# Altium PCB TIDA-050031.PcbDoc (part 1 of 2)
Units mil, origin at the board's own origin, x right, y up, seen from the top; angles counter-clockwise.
Board outline 3300 x 2400 mil, 4 copper layers (Top Layer, Signal Layer 1, Signal Layer 2, Bottom Layer), stack 65.634 mil thick; 87 components, 39 nets, 206 pads, 178 vias.
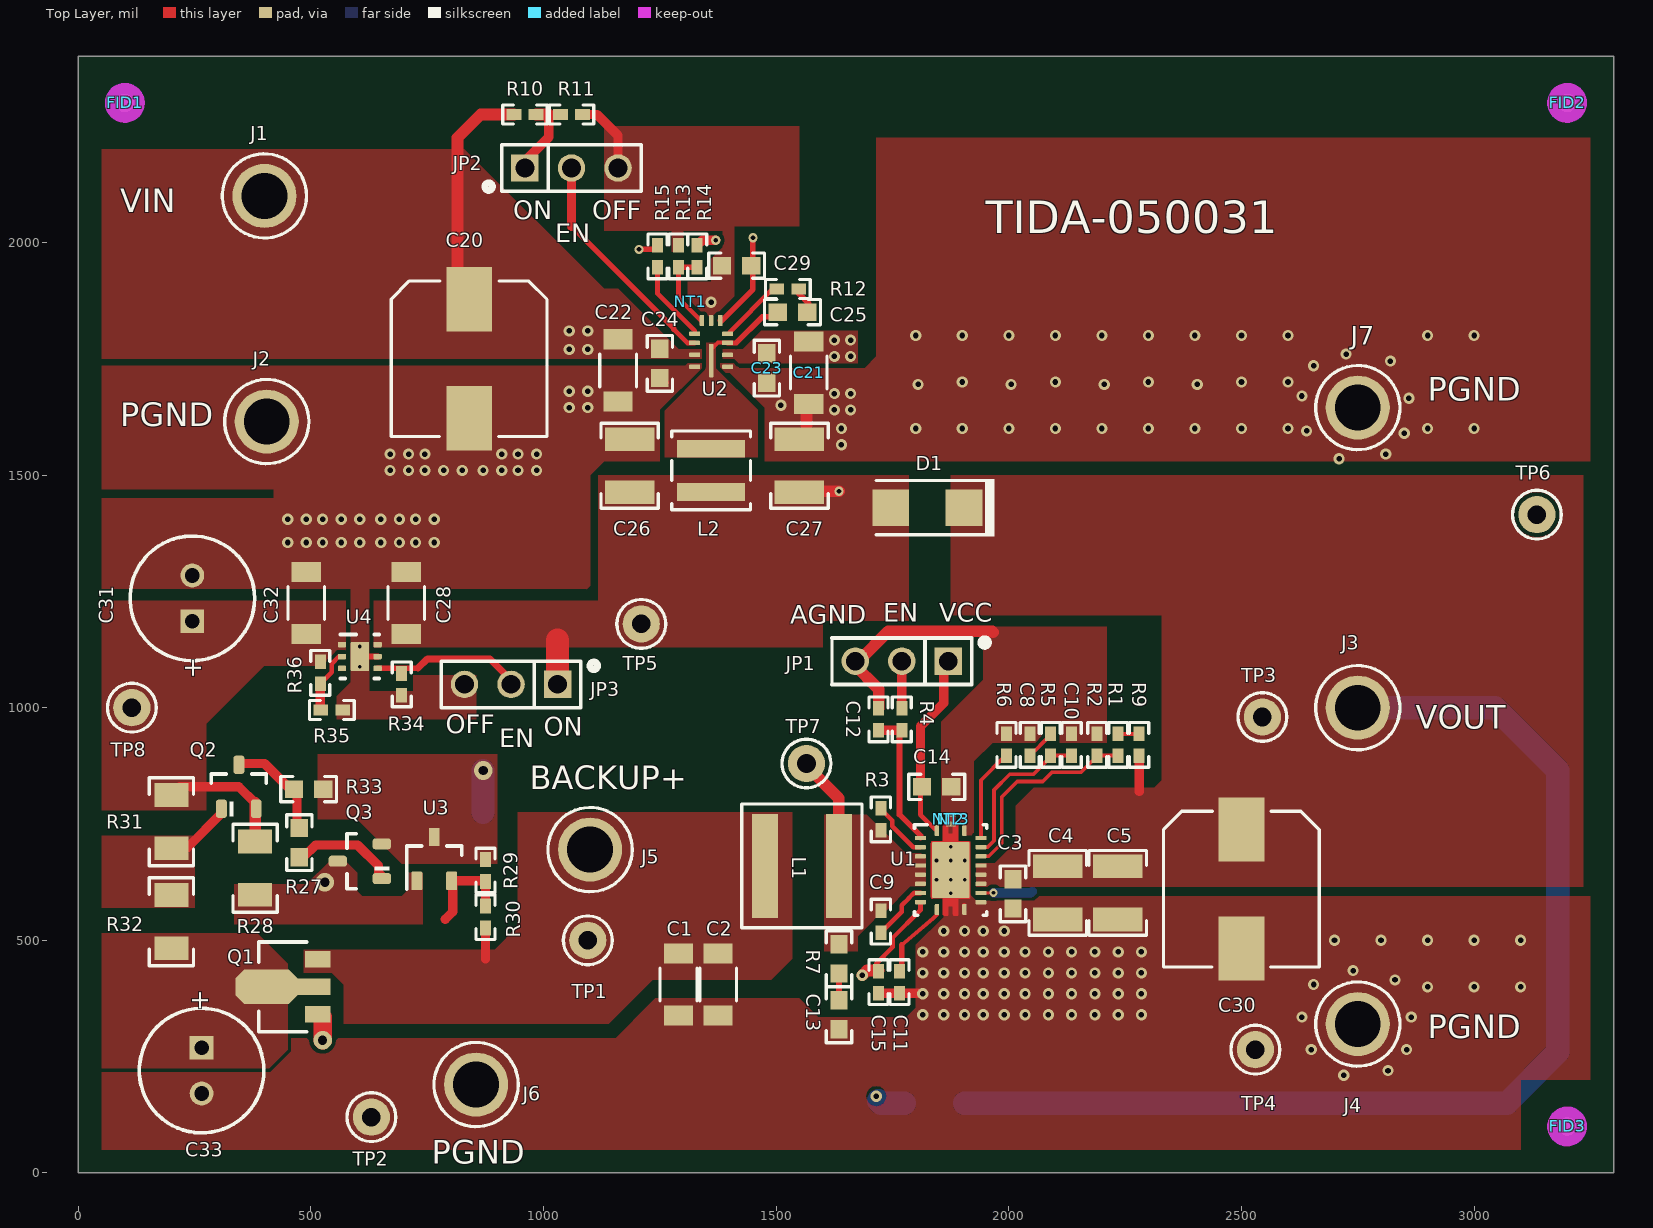
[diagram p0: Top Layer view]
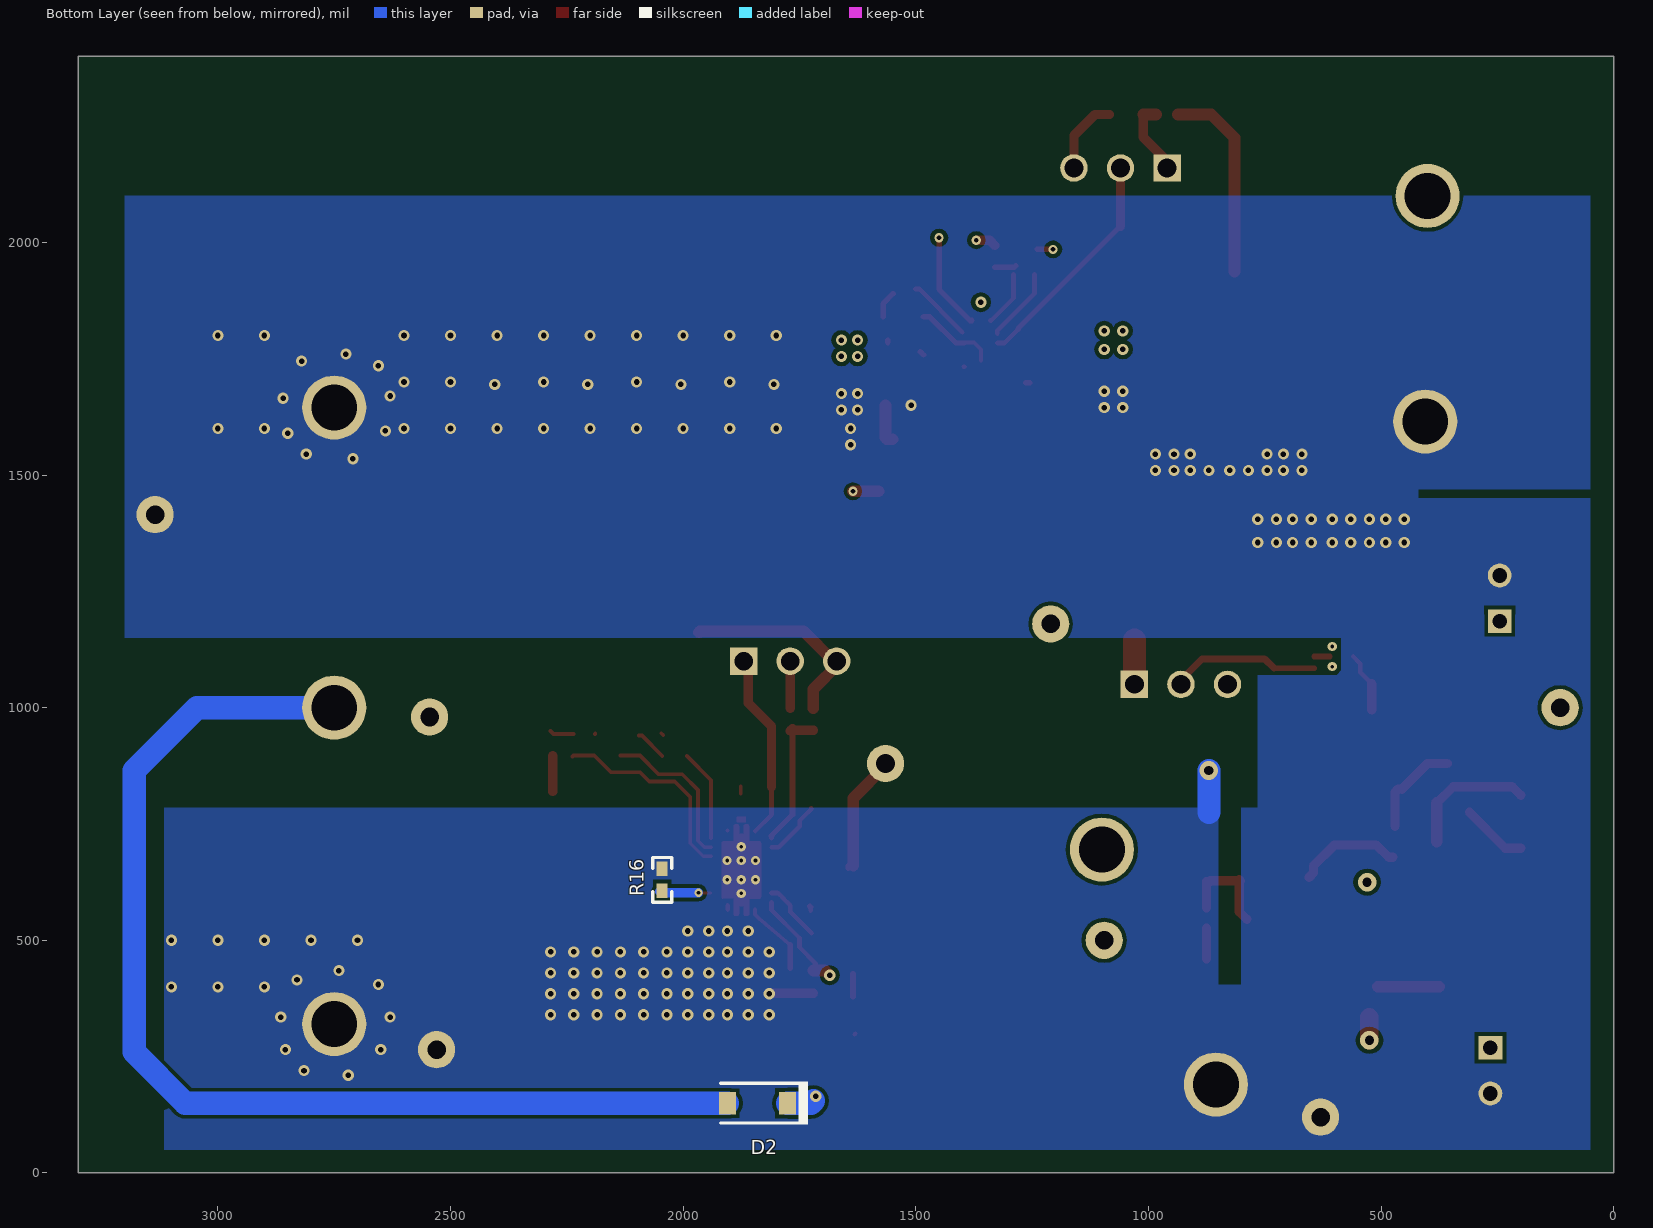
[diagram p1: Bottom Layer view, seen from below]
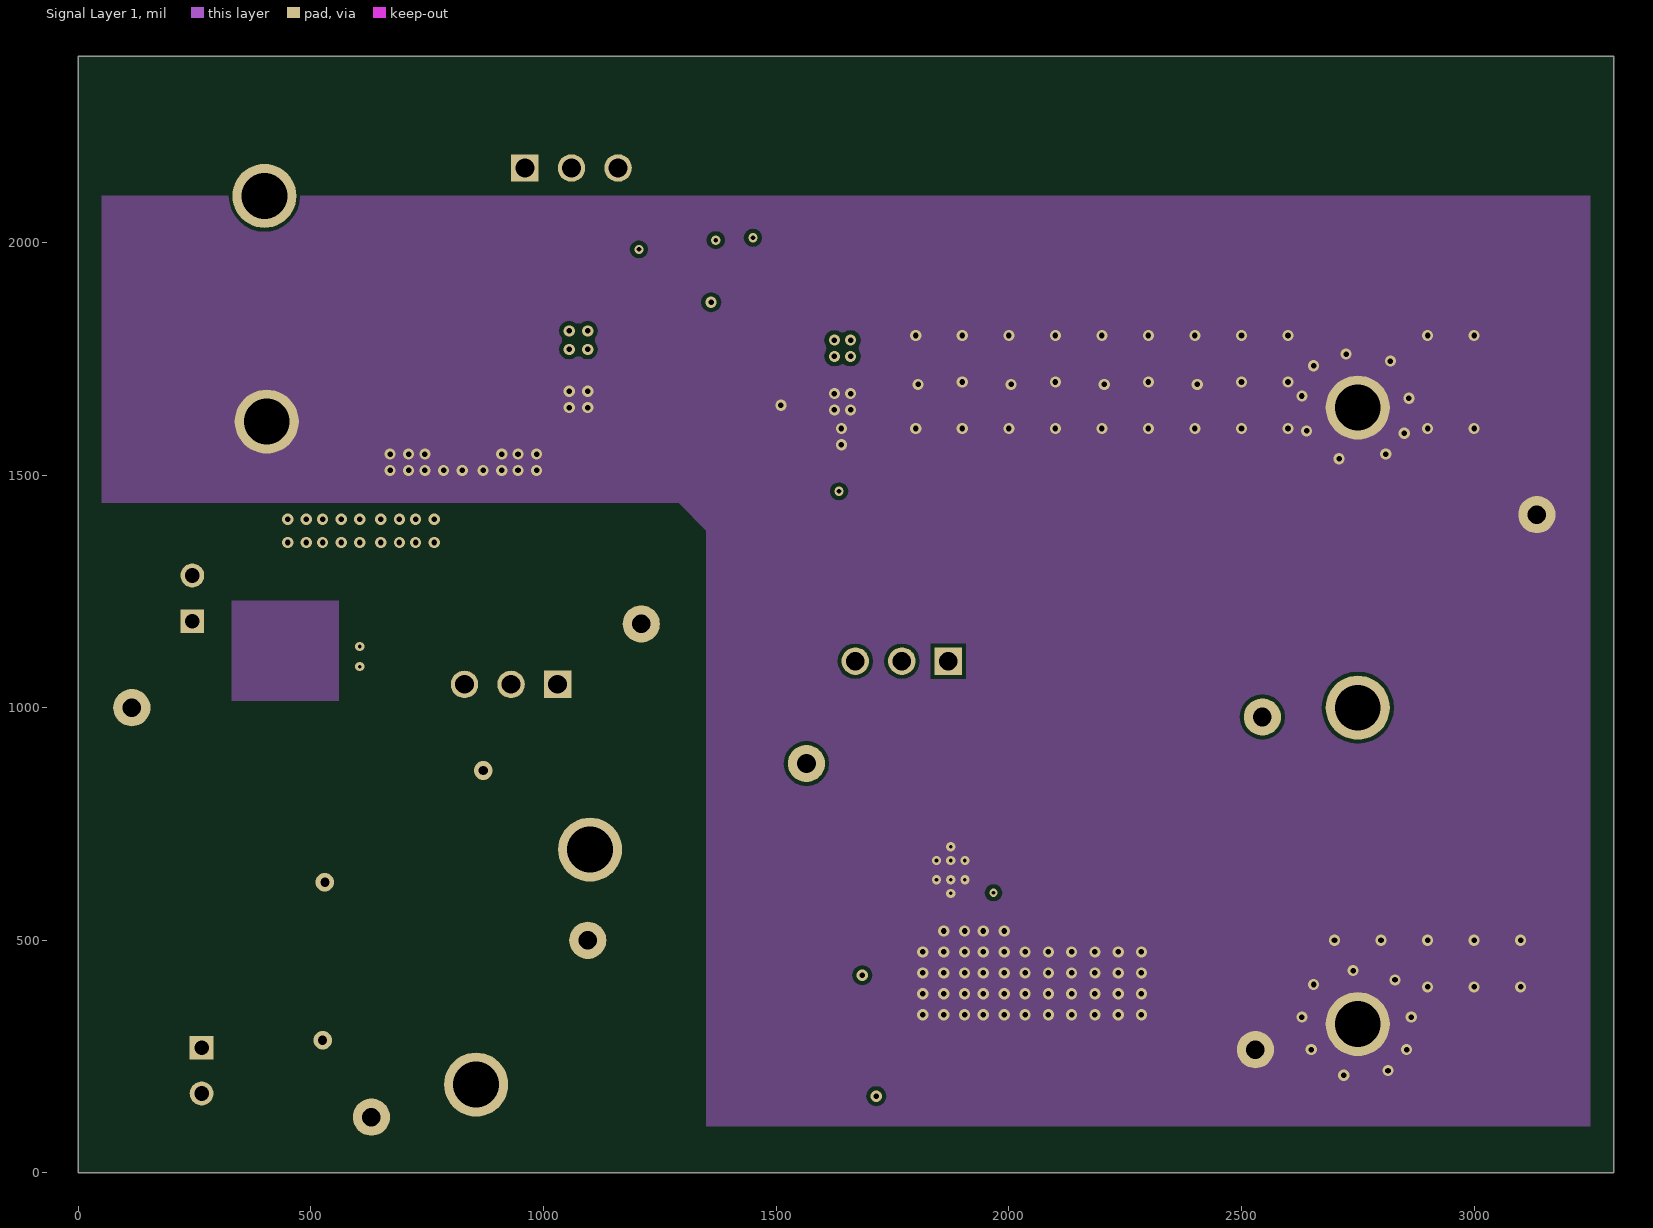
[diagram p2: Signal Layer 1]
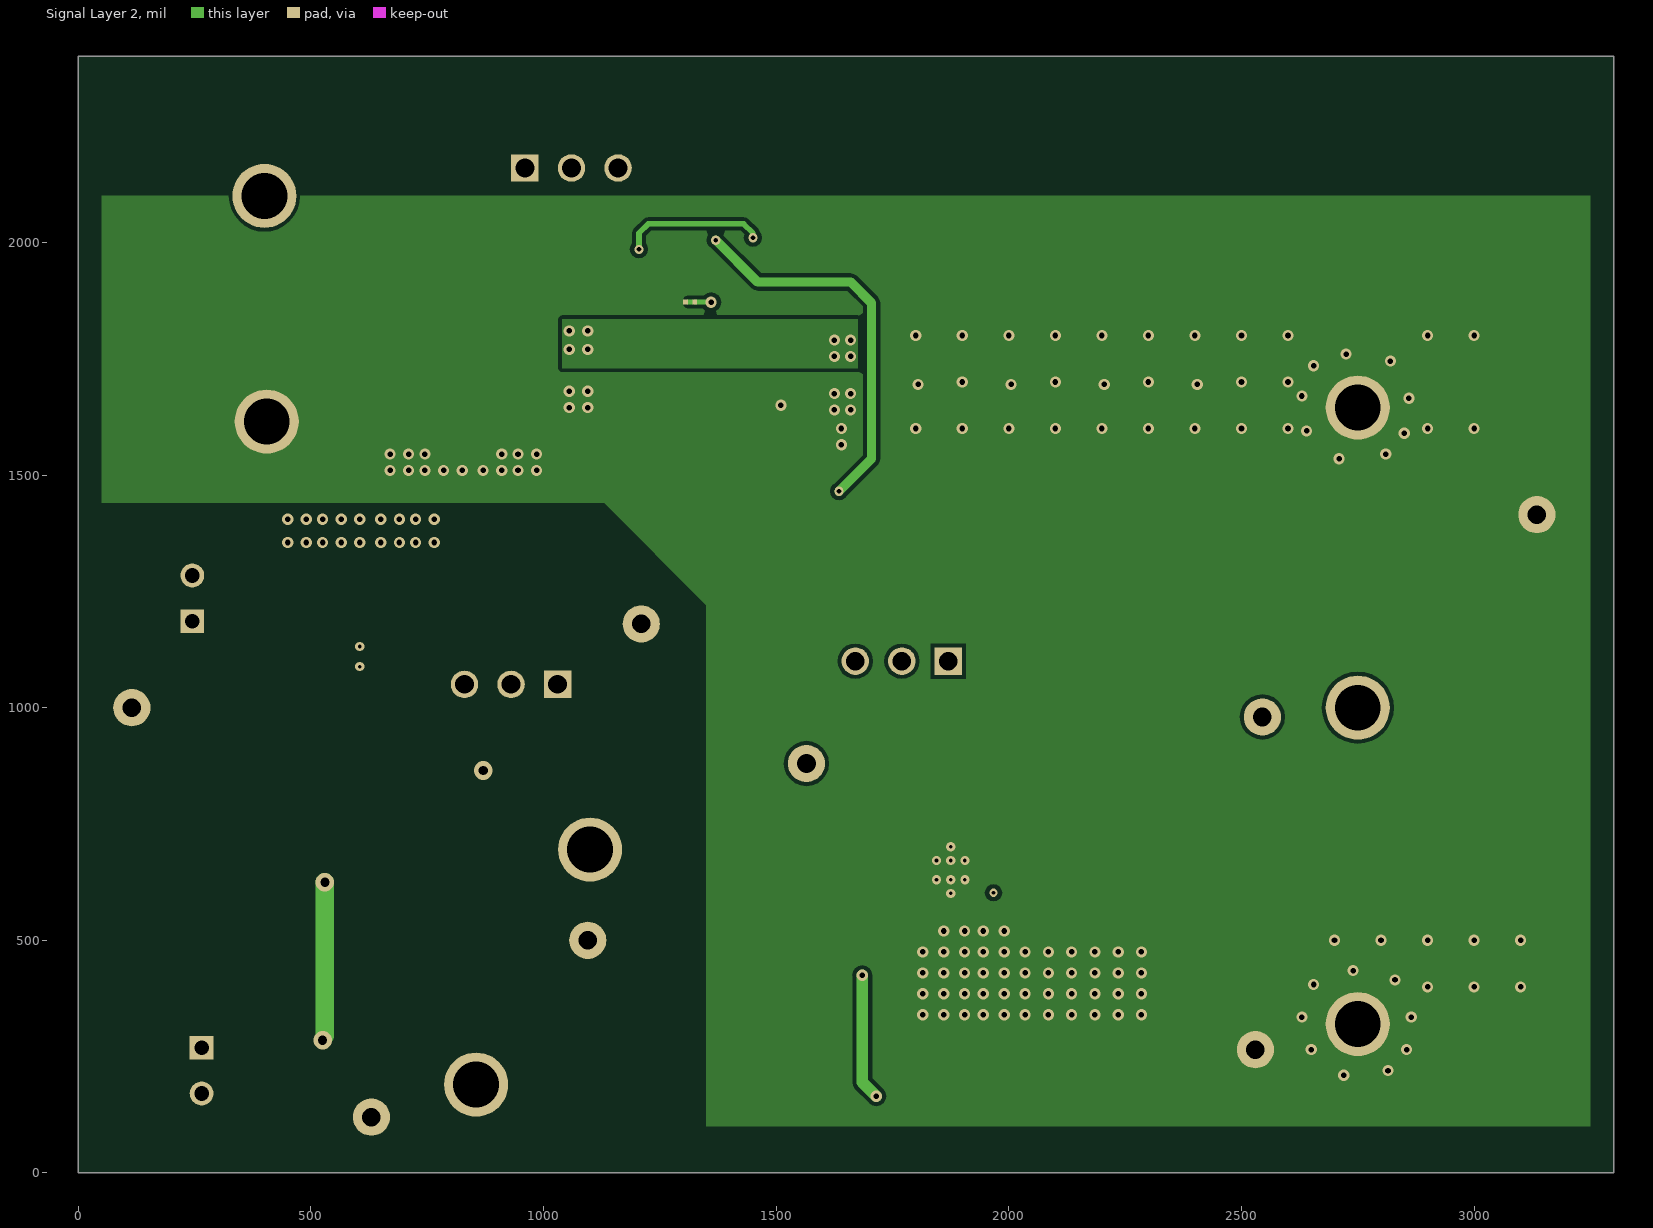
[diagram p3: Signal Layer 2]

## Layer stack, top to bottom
Top Solder: solder mask 0.4, Solder Resist, Dk 3.5
Top Layer: signal copper 1.4
Dielectric 2: core 20, Dk 4.2
Signal Layer 1: signal copper 1.417
Dielectric 3: core 20, Dk 4.2
Signal Layer 2: signal copper 1.417
Dielectric1: core 20, FR-4, Dk 4.8
Bottom Layer: signal copper 1.4
Bottom Solder: solder mask 0.4, Solder Resist, Dk 3.5

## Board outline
0,0 3300,0 3300,2400 0,2400

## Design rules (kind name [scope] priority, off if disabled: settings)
AcuteAngle [All] p1: minimum=4.50000000000000E+0001 checktracksonly=FALSE
AssemblyTestPointUsage [All] p1: valid=2
BoardOutlineClearance BoardOutlineClearance_MountingHoles [OnCopper and InComponentClass('Mounting Holes')] p1: gap=40 ignorepadtopadclearanceinfootprint=FALSE
BoardOutlineClearance BoardOutlineClearance_Poly [OnCopper and IsPoly] p2: gap=25 ignorepadtopadclearanceinfootprint=FALSE
BoardOutlineClearance [OnCopper and Not InComponentClass('Logo') and not InComponentClass('FiducialMark') and not InRegion(1000,500,4000,800) and not InPoly] p3: gap=75 ignorepadtopadclearanceinfootprint=FALSE
Clearance Clearance_Keepouts [((IsTrack Or IsArc) And Not InPoly) And IsFree and IsKeepOut vs ((IsTrack Or IsArc) And Not InPoly) And IsFree and IsKeepOut] p1: gap=0 ignorepadtopadclearanceinfootprint=FALSE
Clearance Clearance_Poly [InPolygon] p2: gap=10 ignorepadtopadclearanceinfootprint=FALSE except(0: Arc-Hole Track-Hole SMDPad-Hole THPad-Hole Via-Hole Fill-Hole Poly-Hole Region-Hole Text-Hole; 8: Arc-Fill Arc-Poly Arc-Region Track-Fill Track-Poly Track-Region SMDPad-Fill SMDPad-Poly SMDPad-Region THPad-Fill THPad-Poly THPad-Region Fill-Fill Fill-Poly Fill-Region Poly-Poly Poly-Region Region-Region; 9: Via-Fill Via-Poly Via-Region)
Clearance Clearance_FiducialMark [IsKeepOut and InComponentClass('FiducialMark') vs IsPad and InComponentClass('FiducialMark')] p3: gap=0 ignorepadtopadclearanceinfootprint=FALSE
Clearance [All] p4: gap=7.87 ignorepadtopadclearanceinfootprint=FALSE except(0: Arc-Hole Track-Hole SMDPad-Hole THPad-Hole Via-Hole Fill-Hole Poly-Hole Region-Hole Text-Hole)
ComponentClearance ComponentClearance_MountingHoles_FiducialMarks [InComponentClass('Mounting Holes') vs InComponentClass('FiducialMark')] p1: gap=0 collisioncheckmode=3 verticalgap=0 showdistances=FALSE
ComponentClearance ComponentClearance_Shunt [InComponentClass('Header') vs InComponentClass('Shunt')] p2: gap=0 collisioncheckmode=3 verticalgap=0 showdistances=FALSE
ComponentClearance ComponentClearance_Logo [InComponentClass('Logo')] p3: gap=10 collisioncheckmode=3 verticalgap=10 showdistances=FALSE
ComponentClearance ComponentClearance_ScrewToNut [(HasFootprint('NY PMS 440 0025 PH')) vs (HasFootprint('Keystone_1902C'))] p4: gap=5 collisioncheckmode=3 verticalgap=10 showdistances=FALSE
ComponentClearance ComponentClearance_MountingHoles [InComponentClass('Mounting Holes')] p5: gap=10 collisioncheckmode=3 verticalgap=100000 showdistances=FALSE
ComponentClearance ComponentClearance_SmallPassives [HasFootprint('0201*') or HasFootprint('0402*') or HasFootprint('0508') or HasFootprint('0603*') or HasFootprint('0612') or HasFootprint('0805*') or HasFootprint('0815*') or HasFootprint('0830*') or HasFootprint('1206*') or HasFootprint('1210*') or HasFootprint('1808*') or HasFootprint('1812*') or HasFootprint('1825*') or HasFootprint('2010*') or HasFootprint('2220*') or HasFootprint('2225*') or HasFootprint('2512*') or HasFootprint('2728*') or HasFootprint('3518*') vs HasFootprint('0201*') or HasFootprint('0402*') or HasFootprint('0508') or HasFootprint('0603*') or HasFootprint('0612') or HasFootprint('0805*') or HasFootprint('0815*') or HasFootprint('0830*') or HasFootprint('1206*') or HasFootprint('1210*') or HasFootprint('1808*') or HasFootprint('1812*') or HasFootprint('1825*') or HasFootprint('2010*') or HasFootprint('2220*') or HasFootprint('2225*') or HasFootprint('2512*') or HasFootprint('2728*') or HasFootprint('3518*')] p6: gap=0 collisioncheckmode=3 verticalgap=10 showdistances=FALSE
ComponentClearance ComponentClearance_THtoSMT [IsThruComponent vs IsSMTComponent] p7: gap=5 collisioncheckmode=3 verticalgap=5 showdistances=FALSE
ComponentClearance ComponentClearance_THtoTH [IsThruComponent vs IsThruComponent] p8: gap=5 collisioncheckmode=3 verticalgap=5 showdistances=FALSE
ComponentClearance [All] p9: gap=0 collisioncheckmode=3 verticalgap=0 showdistances=FALSE
DiffPairsRouting [All] p1: maxlimit=100 minlimit=10 mostfreqgap=10 toplayer_minwidth=15 toplayer_maxwidth=15 toplayer_prefwidth=15 midlayer1_minwidth=15 midlayer1_maxwidth=15 midlayer1_prefwidth=15 midlayer2_minwidth=15 midlayer2_maxwidth=15 midlayer2_prefwidth=15 bottomlayer_minwidth=15 bottomlayer_maxwidth=15 bottomlayer_prefwidth=15 maxuncoupledlength=1000
FabricationTestPointUsage TestPointUsage [All] p1: valid=2 allowmultiple=FALSE
FabricationTestpoint Testpoint [All] p1: side=3 testpointundercomponent=TRUE minsize=40 maxsize=100 preferedsize=60 minholesize=0 maxholesize=40 preferedholesize=32 testpointgrid=1 allowsidetop=TRUE allowsidebottom=TRUE usegrid=TRUE gridtolerance=0.01
FanoutControl Fanout_LCC [IsLCC] p1: bgadir=Out bgaviamode=Centered fanoutstyle=Auto fanoutdirection=Alternating viagrid=1 // Fanout_LCC (Default Rule)
FanoutControl Fanout_BGA [IsBGA] p2: bgadir=Out bgaviamode=Centered fanoutstyle=Auto fanoutdirection=Alternating viagrid=1 // Fanout_BGA (Default Rule)
FanoutControl Fanout_Default [All] p4: bgadir=Out bgaviamode=Centered fanoutstyle=Auto fanoutdirection=Alternating viagrid=1 // Fanout_Default (Default Rule)
FanoutControl Fanout_Small [(CompPinCount < 5)] p5: bgadir=Out bgaviamode=Centered fanoutstyle=Auto fanoutdirection=OutThenIn viagrid=1 // Fanout_Small (Default Rule)
HoleSize [All] p1: absolutevalues=TRUE maxlimit=251 minlimit=7.87 maxpercent=80.000 minpercent=20.000
MinimumAnnularRing MinimumAnnularRing_ThermalPadVias [IsVia and InAnyComponent] p1: minimumring=5.91
MinimumAnnularRing [All] p2: minimumring=8
MinimumSolderMaskSliver MinimumSolderMaskSliver_Logo [InComponentClass('Logo') vs InComponentClass('Logo')] p1: minsoldermaskwidth=0.7
MinimumSolderMaskSliver [All] p2: minsoldermaskwidth=3.94
PlaneClearance [All] p1: clearance=15
PlaneConnect [All] p1: planeconnectstyle=Direct reliefexpansion=10 reliefentries=4 reliefconductorwidth=10 reliefairgap=10
PolygonConnect [All] p1: connectstyle=Direct reliefconductorwidth=10 reliefentries=4 polygonreliefangle="90 Angle" airgapwidth=10
RoutingVias ThermalPadVias [IsVia and InAnyComponent] p1: holewidth=7.87 width=19.68 viastyle="Through Hole" minholewidth=7.87 minwidth=19.68 maxholewidth=12.99 maxwidth=23.62
RoutingVias [All] p2: holewidth=16 width=34 viastyle="Through Hole" minholewidth=7.87 minwidth=26 maxholewidth=40 maxwidth=65
SilkToBoardRegionClearance [Not ((IsComment or IsDesignator) And (Hide <> 'False')) and not InRegion(1000,500,4000,800)] p1:
SilkToSilkClearance SilkToSilkClearance_Pb-FreeLogo [(HasFootprint('Pb-Free_Overlay_Medium') OR HasFootprint('Pb-Free_Overlay_Small')) vs (HasFootprint('Pb-Free_Overlay_Medium') OR HasFootprint('Pb-Free_Overlay_Small'))] p1: silktosilkclearance=0
SilkToSilkClearance [All] p2: silktosilkclearance=4
SilkToSolderMaskClearance SilkToComponentPadClearance [(IsPad or IsFill or IsRegion) and InAnycomponent] p1: minsilkscreentomaskgap=5 clearancetoexposedcopper=TRUE
SilkToSolderMaskClearance "Silk to Solder Mask Opening" [All] p2: minsilkscreentomaskgap=4 clearancetoexposedcopper=FALSE
SolderMaskExpansion [All] p1: expansion=1.97
Width [All] p1: maxlimit=100 minlimit=6 preferedwidth=10 checkconnectedcopper=TRUE
14 further rules are at their usual default settings.

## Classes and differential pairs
component class TIDA-050031_Hardware: !PCB FID1 FID2 FID3
component class FiducialMark: FID1 FID2 FID3
component class Header: JP1 JP2 JP3

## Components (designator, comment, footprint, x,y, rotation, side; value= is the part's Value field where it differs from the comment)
C1 "Capacitor" 1206_180 1290,405 r270 top value=22uF
C2 "Capacitor" 1206_180 1375,405 r270 top value=22uF
C3 "Capacitor" 0603 2009,600 r270 top value=1uF
C4 "Capacitor" 1210_270 2105,602 r270 top value=22uF
C5 "Capacitor" 1210_270 2234,602 r270 top value=22uF
C8 "Capacitor" 0402 2045,920 r90 top value=4700pF
C9 "Capacitor" 0402 1725,540 r270 top value=0.1uF
C10 "Capacitor" 0402 2135,920 r90 top value=47pF
C11 "Capacitor" 0402 1765,410 r90 top value=0.047uF
C12 "Capacitor" 0402 1720,975 r90 top value=0.1uF
C13 "Capacitor" 0603 1635,340 r270 top value=1000pF
C14 "Capacitor" 0603 1845,830 r180 top value=4.7uF
C15 "Capacitor" 0402 1720,410 r270 top value=0.1uF
C20 "EEHZA1H680P" SM_RADIAL_8MM 840,1750 r270 top value=68uF
C21 "CGA5L1X7R1H106K160AC" 1206_190 1570,1720 r270 top value=10uF
C22 "CGA5L1X7R1H106K160AC" 1206_190 1160,1725 r270 top value=10uF
C23 "C1608X5R1H105K080AB" 0603 1480,1730 r270 top value=1uF
C24 "C1608X5R1H105K080AB" 0603 1250,1740 r270 top value=1uF
C25 "C1608X5R1H474K080AB" 0603 1535,1850 r0 top value=0.47uF
C26 "Capacitor" 1210_270 1185,1520 r90 top value=22uF
C27 "Capacitor" 1210_270 1550,1520 r90 top value=22uF
C28 "Capacitor" 1206_180 705,1225 r90 top value=22uF
C29 "Capacitor" 0603 1415,1950 r0 top value=4.7uF
C30 "EEHZA1E221P" SM_RADIAL_8MM 2500,610 r270 top value=220uF
C31 "ECA-0JM471B" M_630x1120 245,1235 r90 top value=470uF
C32 "Capacitor" 1206_180 490,1225 r90 top value=22uF
C33 "ECA-0JM471B" M_630x1120 265,220 r270 top value=470uF
D1 "SL12-E3/61T" SMA 1825,1430 r180 top value=20V
D2 "1N4148W-7-F" SOD-123 1840,150 r0 bottom value=100V
FID1 "Fiducial" Fiducial10-20 100,2300 r0 top
FID2 "Fiducial" Fiducial10-20 3200,2300 r0 top
FID3 "Fiducial" Fiducial10-20 3200,100 r0 top
J1 "Suggest using a net name here" Keystone1502-2 400,2100 r0 top value=Double
J2 "Turret" Keystone1502-2 405,1615 r0 top
J3 "Turret" Keystone1502-2 2750,1000 r0 top
J4 "Turret" Keystone1502-2 2750,320 r0 top
J5 "Turret" Keystone1502-2 1100,695 r0 top
J6 "Turret" Keystone1502-2 855,190 r0 top
J7 "Turret" Keystone1502-2 2750,1645 r0 top
JP1 "Header_3x1_Launchpad" CONN_PEC03SAAN 1770,1100 r180 top
JP2 "Header_3x1_Launchpad" CONN_PEC03SAAN 1060,2160 r0 top
JP3 "Header_3x1_Launchpad" CONN_PEC03SAAN 930,1050 r180 top
L1 "Inductor_Iron" XAL6030 1555,660 r0 top value=2.2uH
L2 "XAL4020-222MEB" XAL4020 1360,1510 r270 top value=2.2uH
NT1 "Net-Tie" Net-Tie_10mil#1 1315,1872 r180 top net-tie
NT2 "Net-Tie" Net-Tie_10mil#2 1870,760 r90 top net-tie
NT3 "Net-Tie" Net-Tie_10mil#2 1880,760 r90 top net-tie
Q1 "2DD1664R-13" SOT-89-3 440,400 r180 top value="32 V"
Q2 "BC857C-7-F" SOT-23 345,830 r90 top value="45 V"
Q3 "BC847CLT1G" SOT-23 605,670 r180 top value="45 V"
R1 "CRCW0402280KFKED" 0402 2235,920 r90 top value=280k
R2 "CRCW040249K9FKED" 0402 2190,920 r270 top value=49.9k
R3 "Resistor" 0402 1725,760 r270 top value=392k
R4 "Resistor" 0402 1770,975 r90 top value=0
R5 "Resistor" 0402 2090,920 r270 top value=17.4k
R6 "Resistor" 0402 1995,920 r270 top value=49.9k
R7 "Resistor" 0603 1635,460 r270 top value=2.05
R9 "Resistor" 0402 2280,920 r270 top value=49.9
R10 "CRCW0402402KFKED" 0402 960,2275 r180 top value=402k
R11 "CRCW0402133KFKED" 0402 1060,2275 r180 top value=133k
R12 "RC0402JR-070RL" 0402 1525,1900 r0 top value=0
R13 "CRCW040249K9FKED" 0402 1290,1970 r270 top value=49.9k
R14 "CRCW0402402KFKED" 0402 1330,1970 r90 top value=402k
R15 "Resistor" 0402 1245,1970 r90 top value=17.4k
R16 "Resistor" 0402 2045,630 r90 bottom value=0
R27 "CRCW0603100RFKEA" 0603 475,710 r270 top value=100
R28 "CRCW120633R0JNEA" 1206 380,655 r270 top value=33
R29 "CRCW0402100KFKED" 0402 875,650 r270 top value=100k
R30 "CRCW040240K2FKED" 0402 875,550 r270 top value=40.2k
R31 "RC1206FR-076R49L" 1206 200,755 r270 top value=6.49
R32 "RC1206FR-076R49L" 1206 200,540 r270 top value=6.49
R33 "CRCW0603499RFKEA" 0603 495,825 r180 top value=499
R34 "CRCW0402100KFKED" 0402 695,1050 r90 top value=100k
R35 "CRCW0402165KFKED" 0402 545,995 r180 top value=165k
R36 "CRCW0402499KFKED" 0402 520,1075 r90 top value=499k
TP1 "5003" Keystone5003 1095,500 r90 top value=Orange
TP2 "5003" Keystone5003 630,120 r90 top value=Orange
TP3 "5003" Keystone5003 2545,980 r90 top value=Orange
TP4 "5003" Keystone5003 2530,265 r0 top value=Orange
TP5 "5003" Keystone5003 1210,1180 r90 top value=Orange
TP6 "5003" Keystone5003 3135,1415 r90 top value=Orange
TP7 "5003" Keystone5003 1565,880 r270 top value=Orange
TP8 "5003" Keystone5003 115,1000 r90 top value=Orange
U1 "TPS61088QRHLRQ1" RHL0020A 1875,651 r0 top
U2 "LMR33630AQRNXRQ1" RNX0012B 1360,1777.09 r180 top
U3 "ATL431AIDBZR" DBZ0003A_N 765,675 r90 top
U4 "TPS7A2501DRVR" DRV0006A 605,1110 r0 top

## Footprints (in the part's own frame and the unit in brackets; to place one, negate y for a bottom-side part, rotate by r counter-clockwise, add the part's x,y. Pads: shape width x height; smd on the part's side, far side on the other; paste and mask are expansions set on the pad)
0402 [mm] "0402 from SM-752 data"
  rect 0.8x0.6 smd: 1(-0.6,0) 2(0.6,0)
  silkscreen extent -1.22,-0.52 1.22,0.52, body extent -0.55,-0.3 0.55,0.3, height 0.6
0603 [mm] "0603 from SM-752 data"
  rect 1x0.95 smd: 1(-0.8,0) 2(0.8,0)
  silkscreen extent -1.52,-0.69 1.52,0.69, body extent -0.87,-0.47 0.87,0.47, height 1
1206 [mm] "1206 from SM-752 data"
  rect 1.3x1.85 smd: 1(-1.45,0) 2(1.45,0)
  silkscreen extent -2.4,-1.21 2.4,1.21, body extent -1.7,-0.9 1.7,0.9, height 1.35
1206_180 [mm] "1206_180"
  rect 1.1x1.6 smd: 1(-1.7,0) 2(1.7,0)
  silkscreen extent -0.9,-1 0.9,1, body extent -1.75,-0.95 1.75,0.95, height 1.8
1206_190 [mm] "1206_190"
  rect 1.1x1.6 smd: 1(-1.7,0) 2(1.7,0)
  silkscreen extent -0.9,-1 0.9,1, body extent -1.75,-0.95 1.75,0.95, height 1.9
1210_270 [mm] "1210"
  rect 1.3x2.7 smd: 1(-1.45,0) 2(1.45,0)
  silkscreen extent -2.32,-1.57 2.32,1.57, body extent -1.7,-1.35 1.7,1.35, height 2.7
CONN_PEC03SAAN [mm] "SULLINS"
  rect 1.5x1.5 hole 1.016: 1(-2.54,0)
  round 1.5 hole 1.016: 2(0,0) 3(2.54,0)
  silkscreen extent -4.72,-1.27 3.81,1.27, body extent -3.84,-1.3 3.84,1.3, height 8.38
DBZ0003A_N [mm] "SOT23, 3-Leads, Body 2.9x1.3mm, Pitch 0.95mm, Lead Span 2.4mm, IPC Medium Density"
  rrect17% 1x0.6 smd: 1(-1.2,0.95) 2(-1.2,-0.95) 3(1.2,0)
  silkscreen extent -1.65,-1.5 0.7,1.5, body extent -1.26,-1.46 1.26,1.46, height 0.98
DRV0006A [mm] "SON, 6-Leads, Body 2x2mm, Pitch 0.65mm, Thermal Pad 1.6x1mm, TI Recommended"
  rrect33% 0.45x0.3 smd: 1(-0.975,0.65) 2(-0.975,0) 3(-0.975,-0.65) 4(0.975,-0.65) 5(0.975,0) 6(0.975,0.65)
  rrect14% 1x0.7 on Top Paste: 7(0,-0.45) 7(0,0.45)
  rrect10% 1x1.6 smd paste-0.5: 7(0,0)
  silkscreen extent -1.05,-1.2 1.05,1.2, body extent -1.05,-1.05 1.05,1.05, height 0.81
Fiducial10-20 [mm]
  round 1 smd mask+0.5: 1(0,0)
  Top Layer keep-out circle w1.178: c0,0 r0.5
Keystone1502-2 [mm] "Double Turret"
  round 3.5 hole 2.5: 1(0,0)
  silkscreen extent -2.3,-2.3 2.3,2.3, body extent -1.6,-1.6 1.59,1.6, height 5.62
Keystone5003 [mil] "For Keystone 500x miniature loop terminals"
  round 80 hole 40: 1(0,0)
  silkscreen extent -52,-52 52,52, body extent -49,-49 49,49, height 182
M_630x1120 [mm] "TH, 2-Leads, Dia 6.3mm, Pin Spacing 2.5mm"
  rect 1.3x1.3 hole 0.8: 1(-1.25,0)
  round 1.3 hole 0.8: 2(1.25,0)
  silkscreen extent -3.4,-3.4 3.4,3.4, body extent -3.37,-3.39 3.4,3.39, height 12.21
Net-Tie_10mil#1 [mil] "10mil net tie, no solder mask opening, no solder paste"
  rect 10x10 on Mid2 paste-5 mask-5: 1(-10,0) 2(10,0)
  Signal Layer 2 region: -6,5 6,5 6,-5 -6,-5
Net-Tie_10mil#2 [mil] "10mil net tie, no solder mask opening, no solder paste"
  rect 10x10 smd paste-5 mask-5: 1(-10,0) 2(10,0)
  Top Layer region: -6,5 6,5 6,-5 -6,-5
RHL0020A [mm] "QFN, 20-Leads, Body 4.5x3.5mm, Pitch 0.5mm, Thermal Pad 3.05x2.05mm, TI Recommended"
  rrect42% 0.24x0.6 smd: 1(-0.75,2.15) 10(-0.75,-2.15) 11(0.75,-2.15) 20(0.75,2.15)
  rrect42% 0.6x0.24 smd: 2(-1.65,1.75) 3(-1.65,1.25) 4(-1.65,0.75) 5(-1.65,0.25) 6(-1.65,-0.25) 7(-1.65,-0.75) 8(-1.65,-1.25) 9(-1.65,-1.75) 12(1.65,-1.75) 13(1.65,-1.25) 14(1.65,-0.75) 15(1.65,-0.25) 16(1.65,0.25) 17(1.65,0.75) 18(1.65,1.25) 19(1.65,1.75)
  rrect12% 0.92x0.85 on Top Paste: 21(-0.56,-1.05) 21(-0.56,0) 21(-0.56,1.05) 21(0.56,-1.05) 21(0.56,0) 21(0.56,1.05)
  rrect5% 2.05x3.05 smd paste-2 mask+0: 21(0,0)
  Top Layer region: -0.975,-1.575 -0.425,-1.575 -0.425,-2.4 -0.417,-2.438 -0.396,-2.471 -0.363,-2.492 -0.325,-2.5 -0.325,-2.5 -0.225,-2.5 -0.187,-2.492 -0.154,-2.471 -0.133,-2.438 -0.125,-2.4 -0.125,-2.4 -0.125,-1.975 0.125,-1.975 0.125,-2.4 0.133,-2.438 0.154,-2.471 0.187,-2.492 0.225,-2.5 0.225,-2.5 0.325,-2.5 0.363,-2.492 0.396,-2.471 0.417,-2.438 0.425,-2.4 0.425,-2.4 0.425,-1.575 0.975,-1.575 1.013,-1.567 1.046,-1.546 1.067,-1.513 1.075,-1.475 1.075,-1.475 1.075,1.475 1.067,1.513 1.046,1.546 1.013,1.567 0.975,1.575 0.975,1.575 0.425,1.575 0.425,2.4 0.417,2.438 0.396,2.471 0.363,2.492 0.325,2.5 0.325,2.5 0.225,2.5 0.187,2.492 0.154,2.471 0.133,2.438 0.125,2.4 0.125,2.4 0.125,1.975 -0.125,1.975 -0.125,2.4 -0.133,2.438 -0.154,2.471 -0.187,2.492 -0.225,2.5 -0.225,2.5 -0.325,2.5 -0.363,2.492 -0.396,2.471 -0.417,2.438 -0.425,2.4 -0.425,2.4 -0.425,1.575 -0.975,1.575 -1.013,1.567 -1.046,1.546 -1.067,1.513 -1.075,1.475 -1.075,1.475 -1.075,-1.475 -1.067,-1.513 -1.046,-1.546 -1.013,-1.567 -0.975,-1.575
  silkscreen extent -1.98,-2.47 1.98,2.47, body extent -1.75,-2.25 1.75,2.25, height 1.01
RNX0012B [mm] "VQFN-HR-12"
  rrect40% 0.6x0.25 smd: 1(-0.9,1.125) 2(-0.9,0.475) 3(-0.9,-0.175) 4(-0.9,-0.675) 8(0.9,-0.675) 9(0.9,-0.175) 10(0.9,0.475) 11(0.9,1.125)
  rrect40% 0.25x0.6 smd: 5(-0.5,-1.4) 6(0,-1.4) 7(0.5,-1.4)
  rrect40% 0.25x1.825 smd paste-0.175: 12(0,0.788)
  body extent -1,-1.5 1,1.5, height 1
SM_RADIAL_8MM [mm] "Nichicon 8x10"
  rect 3.5x2.5 smd: 1(-3.25,0) 2(3.25,0)
  silkscreen extent -4.25,-4.25 4.25,4.25, body extent -4.25,-4.25 4.25,4.25, height 10.5
SMA [mm] "Molded Diode, 2-Leads, Body 4.3x2.6mm, IPC Medium Density, based on OnSemi component dimensions and land pattern"
  rect 2x2 smd: 1(-2,0) 2(2,0)
  silkscreen extent -3.66,-1.57 2.79,1.57, body extent -2.6,-1.3 2.6,1.3, height 2.42
SOD-123 [mm] "On Semi recommended land pattern"
  rect 0.915x1.22 smd: 1(-1.637,0) 2(1.637,0)
  silkscreen extent -2.74,-1.17 2.03,1.17, body extent -1.93,-0.9 1.93,0.9, height 1.35
SOT-23 [mm] "SOT23, 3-Leads, Body 2.9x1.3mm, Pitch 0.95mm, Lead Span 2.5mm, IPC Medium Density"
  rrect50% 1x0.6 smd: 1(-1.2,0.95) 2(-1.2,-0.95) 3(1.2,0)
  silkscreen extent -1.63,-1.5 0.7,1.5, body extent -1.16,-1.45 1.21,1.45, height 1
SOT-89-3 [mm] "SOT, 3-Leads, Body 4.6 x 2.6 mm, Pitch 1.5mm"
  rect 1.4x0.9 smd: 1(-1.9,1.5) 3(-1.9,-1.5)
  rect 1.8x0.9 smd: 2(-1.7,0)
  oct 3.4x1.9 smd: 4(0.9,0)
  silkscreen extent -1.3,-2.45 1.33,2.45, body extent -2.42,-2.28 1.83,2.32, height 1.62
XAL4020 [mil] "Coilcraft XAL4020 7/18/12"
  rect 38x146 smd: 1(-46.5,0) 2(46.5,0)
  silkscreen extent -85,-85 85,85, body extent -84,-84 84,84, height 83
XAL6030 [mil] "Coilcraft recommended land pattern Document 887-4 Revised 11/20/12"
  rect 56x224 smd: 1(-79.5,0) 2(79.5,0)
  silkscreen extent -129,-133 129,133, body extent -129,-133 129,133, height 122

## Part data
C1 C2 C28 C32: library part CMP-0008946-2, "CAP, CERM, 22 uF, 16 V, +/- 10%, X5R, 1206", Cap_Case=1206, Manufacturer=MuRata, PartNumber=GRM31CR61C226KE15L, Supplier Part Number 1=GRM31CR61C226KE15L-ND, TempCo=X5R, Tolerance_%=10%, Value1=Unknown, Value2=16V, ValueDisplayed=22uF
C3: library part CMP-0007405-4, "CAP, CERM, 1 uF, 25 V, +/- 10%, X7R, 0603", Cap_Case=0603, Manufacturer=MuRata, PartNumber=GRM188R71E105KA12D, Supplier Part Number 1=490-5307-1-ND, TempCo=X7R, Tolerance_%=10%, Value1=Unknown, Value2=25V, ValueDisplayed=1uF
C4 C5 C26 C27: library part CMP-0009224-2, "CAP, CERM, 22 uF, 25 V, +/- 10%, X7R, 1210", Cap_Case=1210, Manufacturer=MuRata, PartNumber=GRM32ER71E226KE15L, Supplier Part Number 1=490-5313-1-ND, TempCo=X7R, Tolerance_%=10%, Value1=Unknown, Value2=25V, ValueDisplayed=22uF
C8: library part CMP-0006616-2, "CAP, CERM, 4700 pF, 50 V, +/- 10%, X5R, 0402", Cap_Case=0402, Manufacturer=MuRata, PartNumber=GRM155R61H472KA01D, Supplier Part Number 1=GRM155R61H472KA01D-ND, TempCo=X5R, Tolerance_%=10%, Value1=Unknown, Value2=50V, ValueDisplayed=4700pF
C9 C12 C15: library part CMP-0006591-2, "CAP, CERM, 0.1 uF, 16 V, +/- 10%, X5R, 0402", Cap_Case=0402, Manufacturer=MuRata, PartNumber=GRM155R61C104KA88D, Supplier Part Number 1=490-5415-1-ND, TempCo=X5R, Tolerance_%=10%, Value1=Unknown, Value2=16V, ValueDisplayed=0.1uF
C10: library part CMP-0006467-2, "CAP, CERM, 47 pF, 50 V, +/- 1%, C0G/NP0, 0402", Cap_Case=0402, Manufacturer=MuRata, PartNumber=GRM1555C1H470FA01D, Supplier Part Number 1=490-6241-1-ND, TempCo=C0G/NP0, Tolerance_%=1%, Value1=Unknown, Value2=50V, ValueDisplayed=47pF
C11: library part CMP-0006653-2, "CAP, CERM, 0.047 uF, 16 V, +/- 10%, X7R, 0402", Cap_Case=0402, Manufacturer=MuRata, PartNumber=GRM155R71C473KA01D, Supplier Part Number 1=GRM155R71C473KA01D-ND, TempCo=X7R, Tolerance_%=10%, Value1=Unknown, Value2=16V, ValueDisplayed=0.047uF
C13: library part CMP-0007467-4, "CAP, CERM, 1000 pF, 100 V, +/- 10%, X7R, 0603", Cap_Case=0603, Manufacturer=MuRata, PartNumber=GRM188R72A102KA01D, Supplier Part Number 1=490-1472-1-ND, TempCo=X7R, Tolerance_%=10%, Value1=Unknown, Value2=100V, ValueDisplayed=1000pF
C14 C29: library part CMP-0006816-5, "CAP, CERM, 4.7 uF, 10 V, +/- 10%, X5R, 0603", Cap_Case=0603, Manufacturer=AVX, PartNumber=0603ZD475KAT2A, Supplier Part Number 1=478-7943-1-ND, TempCo=X5R, Tolerance_%=10%, Value1=Unknown, Value2=10V, ValueDisplayed=4.7uF
C20: library part CMP-0012579-3, "CAP, Polymer Hybrid, 68 uF, 50 V, +/- 20%, 30 ohm, 8x10 SMD", Manufacturer=Panasonic, Supplier Part Number 1=P15445CT-ND, Tolerance_%=20%, Value1="30 ohm", Value2=50V, ValueDisplayed=68uF
C21 C22: library part CMP-0085950-1, "CAP, CERM, 10 µF, 50 V,+/- 10%, X7R, AEC-Q200 Grade 1, 1206", Cap_Case=1206, Manufacturer=TDK, TempCo=X7R, Tolerance_%=10%, Value2=50V, ValueDisplayed=10µF
C23 C24: "CAP, CERM, 1 µF, 50 V,+/- 10%, X5R, 0603", Cap_Case=0603, Manufacturer=TDK, Supplier Part Number 1=445-7468-1-ND, TempCo=X5R, Tolerance_%=10, Value1="0.005522 ohm", Value2=50V, ValueDisplayed=1µF
C25: "CAP, CERM, 0.47 µF, 50 V,+/- 10%, X5R, 0603", Cap_Case=0603, Manufacturer=TDK, Supplier Part Number 1=445-7464-1-ND, TempCo=X5R, Tolerance_%=10, Value1="0.010974 ohm", Value2=50V, ValueDisplayed=0.47µF
C30: library part CMP-0012571-3, "CAP, Polymer Hybrid, 220 uF, 25 V, +/- 20%, 27 ohm, 8x10 SMD", Manufacturer=Panasonic, Supplier Part Number 1=P15437CT-ND, Tolerance_%=20%, Value1="27 ohm", Value2=25V, ValueDisplayed=220uF
C31 C33: "CAP, AL, 470 µF, 6.3 V, +/- 20%, TH", Cap_Case=6.3x11.2mm, Manufacturer=Panasonic, Supplier Part Number 1=P10358TB-ND, Tolerance_%=20, Value2=6.3V, ValueDisplayed=470µF
D1: "Diode, Schottky, 20 V, 1.5 A, SMA", Manufacturer=Vishay-Semiconductor, Supplier Part Number 1=SL13-E3/61TGICT-ND, Value1=1.5A, Value2=0.445V
D2: "Diode, Ultrafast, 100 V, 0.15 A, SOD-123", Manufacturer="Diodes Inc.", Supplier Part Number 1=1N4148W-FDICT-ND, Value1=0.15A, Value2=1.25V
FID1 FID2 FID3: library part CMP-0077181-1, "Fiducial mark.  There is nothing to buy or mount.", Manufacturer=N/A
J1: library part 1502-2, "Terminal, Turret, TH, Double", Manufacturer=Keystone, Supplier Part Number 1=1502-2K-ND
J2 J3 J4 J5 J6 J7: library part CMP-0055113-1, "Terminal, Turret, TH, Double", Manufacturer=Keystone, PartNumber=1502-2, Supplier Part Number 1=36-1502-2-ND
JP1 JP2 JP3: library part CMP-0002338-1, "Header, 100mil, 3x1, Tin, TH", Color=Black, Current_A=3A, Manufacturer="Sullins Connector Solutions", PartNumber=PEC03SAAN, Supplier Part Number 1=S1012E-03-ND, Voltage_V=1.8kV
L1: library part CMP-0061015-1, "Inductor, Shielded, Composite, 2.2 uH, 12.7 A, 0.012 ohm, SMD", Manufacturer=Coilcraft, PartNumber=XAL6030-222MEB, Value1="0.012 ohm", Value2=12.7A, ValueDisplayed=2.2uH
L2: "Inductor, Shielded, Composite, 2.2 µH, 5.5 A, 0.04 ohm, SMD", Manufacturer=Coilcraft, Value1="0.04 ohm", Value2=5.5A, ValueDisplayed=2.2µH
NT1 NT2 NT3: library part CMP-0078142-1, "Single point connection between nets.", Manufacturer=N/A
Q1: library part "2DD1664R-13, Diodes Inc.", "Transistor, NPN, 32 V, 1 A, SOT-89", Manufacturer="Diodes Inc.", Supplier Part Number 1=2DD1664RDICT-ND, Value1="1 A", Value2=390
Q2: library part "BC857C-7-F, Diodes Inc.", "Transistor, PNP, 45 V, 0.1 A, SOT-23", Manufacturer="Diodes Inc.", Supplier Part Number 1=BC857C-FDICT-ND, Value1="0.1 A", Value2=600
Q3: library part "BC847CLT1G, ON Semiconductor", "Transistor, NPN, 45 V, 0.1 A, SOT-23", Manufacturer="ON Semiconductor", Supplier Part Number 1=BC847CLT1GOSCT-ND, Value1="0.1 A", Value2=800
R1: "RES, 280 k, 1%, 0.063 W, 0402", Manufacturer=Vishay-Dale, Power_W=0.063, Supplier Part Number 1=541-280KLCT-ND, TempCo="100 ppm/C", Tolerance_%=1, Value1=1%, Value2=0.063W, Value_Code=280k
R2 R13: "RES, 49.9 k, 1%, 0.063 W, 0402", Manufacturer=Vishay-Dale, Power_W=0.063, Supplier Part Number 1=541-49.9KLCT-ND, TempCo="100 ppm/C", Tolerance_%=1, Value1=1%, Value2=0.063W, Value_Code=49k9, ValueDisplayed=49.9k
R3: library part CMP-0026325-2, "RES, 392 k, 1%, 0.063 W, AEC-Q200 Grade 0, 0402", Manufacturer=Vishay-Dale, PartNumber=CRCW0402392KFKED, Power_W=63mW, Supplier Part Number 1=541-392KLCT-ND, TempCo="100 ppm/C", Tolerance_%=1%, Value2=0.063W, Value_Code=392k
R4 R16: library part CMP-0027004-2, "RES, 0, 5%, 0.063 W, 0402", Manufacturer="Yageo America", PartNumber=RC0402JR-070RL, Power_W=63mW, Supplier Part Number 1=311-0.0JRCT-ND, TempCo="200 ppm/C", Tolerance_%=5%, Value2=0.063W, Value_Code=0000, ValueDisplayed=0
R5 R15: library part CMP-0026050-3, "RES, 17.4 k, 1%, 0.063 W, AEC-Q200 Grade 0, 0402", Manufacturer=Vishay-Dale, PartNumber=CRCW040217K4FKED, Power_W=63mW, Supplier Part Number 1=541-17.4KLCT-ND, TempCo="100 ppm/C", Tolerance_%=1%, Value2=0.063W, Value_Code=17k4, ValueDisplayed=17.4k
R6: library part CMP-0026403-2, "RES, 49.9 k, 1%, 0.063 W, AEC-Q200 Grade 0, 0402", Manufacturer=Vishay-Dale, PartNumber=CRCW040249K9FKED, Power_W=63mW, Supplier Part Number 1=541-49.9KLCT-ND, TempCo="100 ppm/C", Tolerance_%=1%, Value2=0.063W, Value_Code=49k9, ValueDisplayed=49.9k
R7: library part CMP-0022303-4, "RES, 2.05, 1%, 0.1 W, AEC-Q200 Grade 0, 0603", Manufacturer=Vishay-Dale, PartNumber=CRCW06032R05FKEA, Power_W=100mW, Supplier Part Number 1=541-2.05HHCT-ND, TempCo="100 ppm/C", Tolerance_%=1%, Value2=0.1W, Value_Code=2R05, ValueDisplayed=2.05
R9: library part CMP-0026404-2, "RES, 49.9, 1%, 0.063 W, AEC-Q200 Grade 0, 0402", Manufacturer=Vishay-Dale, PartNumber=CRCW040249R9FKED, Power_W=63mW, Supplier Part Number 1=541-49.9LCT-ND, TempCo="100 ppm/C", Tolerance_%=1%, Value2=0.063W, Value_Code=49R9, ValueDisplayed=49.9
R10 R14: "RES, 402 k, 1%, 0.063 W, 0402", Manufacturer=Vishay-Dale, Power_W=0.063, Supplier Part Number 1=541-402KLCT-ND, TempCo="100 ppm/C", Tolerance_%=1, Value1=1%, Value2=0.063W, Value_Code=402k
R11: "RES, 133 k, 1%, 0.063 W, 0402", Manufacturer=Vishay-Dale, Power_W=0.063, Supplier Part Number 1=541-133KLCT-ND, TempCo="100 ppm/C", Tolerance_%=1, Value1=1%, Value2=0.063W, Value_Code=133k
R12: "RES, 0, 5%, 0.063 W, 0402", Manufacturer="Yageo America", Power_W=0.063, Supplier Part Number 1=311-0.0JRCT-ND, TempCo="200 ppm/C", Tolerance_%=5, Value1=5%, Value2=0.063W, Value_Code=0000, ValueDisplayed=0
R27: "RES, 100, 1%, 0.1 W, 0603", Manufacturer=Vishay-Dale, Power_W=0.1, Supplier Part Number 1=541-100HCT-ND, TempCo="100 ppm/C", Tolerance_%=1, Value1=1%, Value2=0.1W, Value_Code=100R, ValueDisplayed=100
R28: "RES, 33, 5%, 0.25 W, 1206", Manufacturer=Vishay-Dale, Power_W=0.25, Supplier Part Number 1=541-33ECT-ND, TempCo="200 ppm/C", Tolerance_%=5, Value1=5%, Value2=0.25W, Value_Code=33R0, ValueDisplayed=33
R29 R34: "RES, 100 k, 1%, 0.063 W, 0402", Manufacturer=Vishay-Dale, Power_W=0.063, Supplier Part Number 1=541-100KLCT-ND, TempCo="100 ppm/C", Tolerance_%=1, Value1=1%, Value2=0.063W, Value_Code=100k
R30: "RES, 40.2 k, 1%, 0.063 W, 0402", Manufacturer=Vishay-Dale, Power_W=0.063, Supplier Part Number 1=541-40.2KLCT-ND, TempCo="100 ppm/C", Tolerance_%=1, Value1=1%, Value2=0.063W, Value_Code=40k2, ValueDisplayed=40.2k
R31 R32: "RES, 6.49, 1%, 0.25 W, 1206", Manufacturer="Yageo America", Power_W=0.25, Supplier Part Number 1=311-6.49FRCT-ND, TempCo="200 ppm/C", Tolerance_%=1, Value1=1%, Value2=0.25W, Value_Code=6R49, ValueDisplayed=6.49
R33: "RES, 499, 1%, 0.1 W, 0603", Manufacturer=Vishay-Dale, Power_W=0.1, Supplier Part Number 1=541-499HCT-ND, TempCo="100 ppm/C", Tolerance_%=1, Value1=1%, Value2=0.1W, Value_Code=499R, ValueDisplayed=499
R35: "RES, 165 k, 1%, 0.063 W, 0402", Manufacturer=Vishay-Dale, Power_W=0.063, Supplier Part Number 1=541-165KLCT-ND, TempCo="100 ppm/C", Tolerance_%=1, Value1=1%, Value2=0.063W, Value_Code=165k
R36: "RES, 499 k, 1%, 0.063 W, 0402", Manufacturer=Vishay-Dale, Power_W=0.063, Supplier Part Number 1=541-499KLCT-ND, TempCo="100 ppm/C", Tolerance_%=1, Value1=1%, Value2=0.063W, Value_Code=499k
TP1 TP2 TP3 TP4 TP5 TP6 TP7 TP8: "Test Point, Miniature, Orange, TH", Manufacturer=Keystone, Supplier Part Number 1=36-5003-ND
U1: library part CMP-0082345-1, "10-A Fully-Integrated Synchronous Boost Converter, RHL0020A (VQFN-20)", Alternate Manufacturer="Texas Instruments", Alternate PartNumber=TPS61088QRHLTQ1, Operating Temperature Range="-40 to 125 C", Rating=Automotive
U2: library part CMP-0078601-4, "Automotive 3.8-V to 36-V 3-A Synchronous Step-Down Voltage Regulator, RNX0012B (VQFN-HR-12)", Alternate Manufacturer="Texas Instruments", Alternate PartNumber=LMR33630AQRNXTQ1
U3: "2.5V Low Iq Adjustable Precision Shunt Regulator, DBZ0003A (SOT-23-3)", Alternate Manufacturer="Texas Instruments"
U4: library part CMP-0078340-1, "300-mA, 18-V, Low IQ, Low Dropout Voltage Regulator with Power Good, DRV0006A (WSON-6)", Alternate Manufacturer="Texas Instruments"

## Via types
v1: diameter 24, hole 12, Top Layer to Bottom Layer, 156 vias
v2: diameter 19.68, hole 7.87, Top Layer to Bottom Layer, 10 vias
v3: diameter 20, hole 10, Top Layer to Bottom Layer, 4 vias
v4: diameter 24, hole 12, Top Layer to Bottom Layer, tented bottom, 4 vias
v5: diameter 40, hole 20, Top Layer to Bottom Layer, 3 vias
v6: diameter 18, hole 8, Top Layer to Bottom Layer, 1 vias

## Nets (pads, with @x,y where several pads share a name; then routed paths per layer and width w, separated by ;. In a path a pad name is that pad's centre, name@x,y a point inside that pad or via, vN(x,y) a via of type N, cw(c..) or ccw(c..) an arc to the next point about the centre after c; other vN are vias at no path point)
2.5V: R29.2 R30.1 U3.2 | length 216.9
  Top Layer w20: 788.62,545 805,561.38 U3.2@805,627.76 ; U3.2@802.4,627.76 U3.2@805,627.76 ; U3.2@805,630 U3.2@805,627.76 ; R29.2@870,625 867.24,627.76 U3.2@805,627.76 ; R30.1@875,570 R30.1@875,573.62 R29.2@875,626.38
5V: C31.1 C32.1 Q2.2 R28.1 R31.1 R36.2 TP8.1 U4.1 | length 284.8
  Top Layer w20: R31.1@200,812.09 217.91,830 345,830 Q2.2@380,795
  Top Layer w25: R28.1@380,712.09 Q2.2@380,795
9V: C26.1 C27.1 C28.1 D1.2 JP3.1 L2.2 R14.2 TP5.1 U4.6 | length 1019.6
  Top Layer w20: R14.2@1330,1993.62 1341.38,2005 v3(1370,2005)
  Top Layer w25: C27.1@1580,1465 v3(1635,1465)
  Top Layer w50: JP3.1@1030,1050 1030,1145
  Signal Layer 2 w20: v3(1370,2005) 1460,1915 1660,1915 1705,1870 1705,1535 v3(1635,1465)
